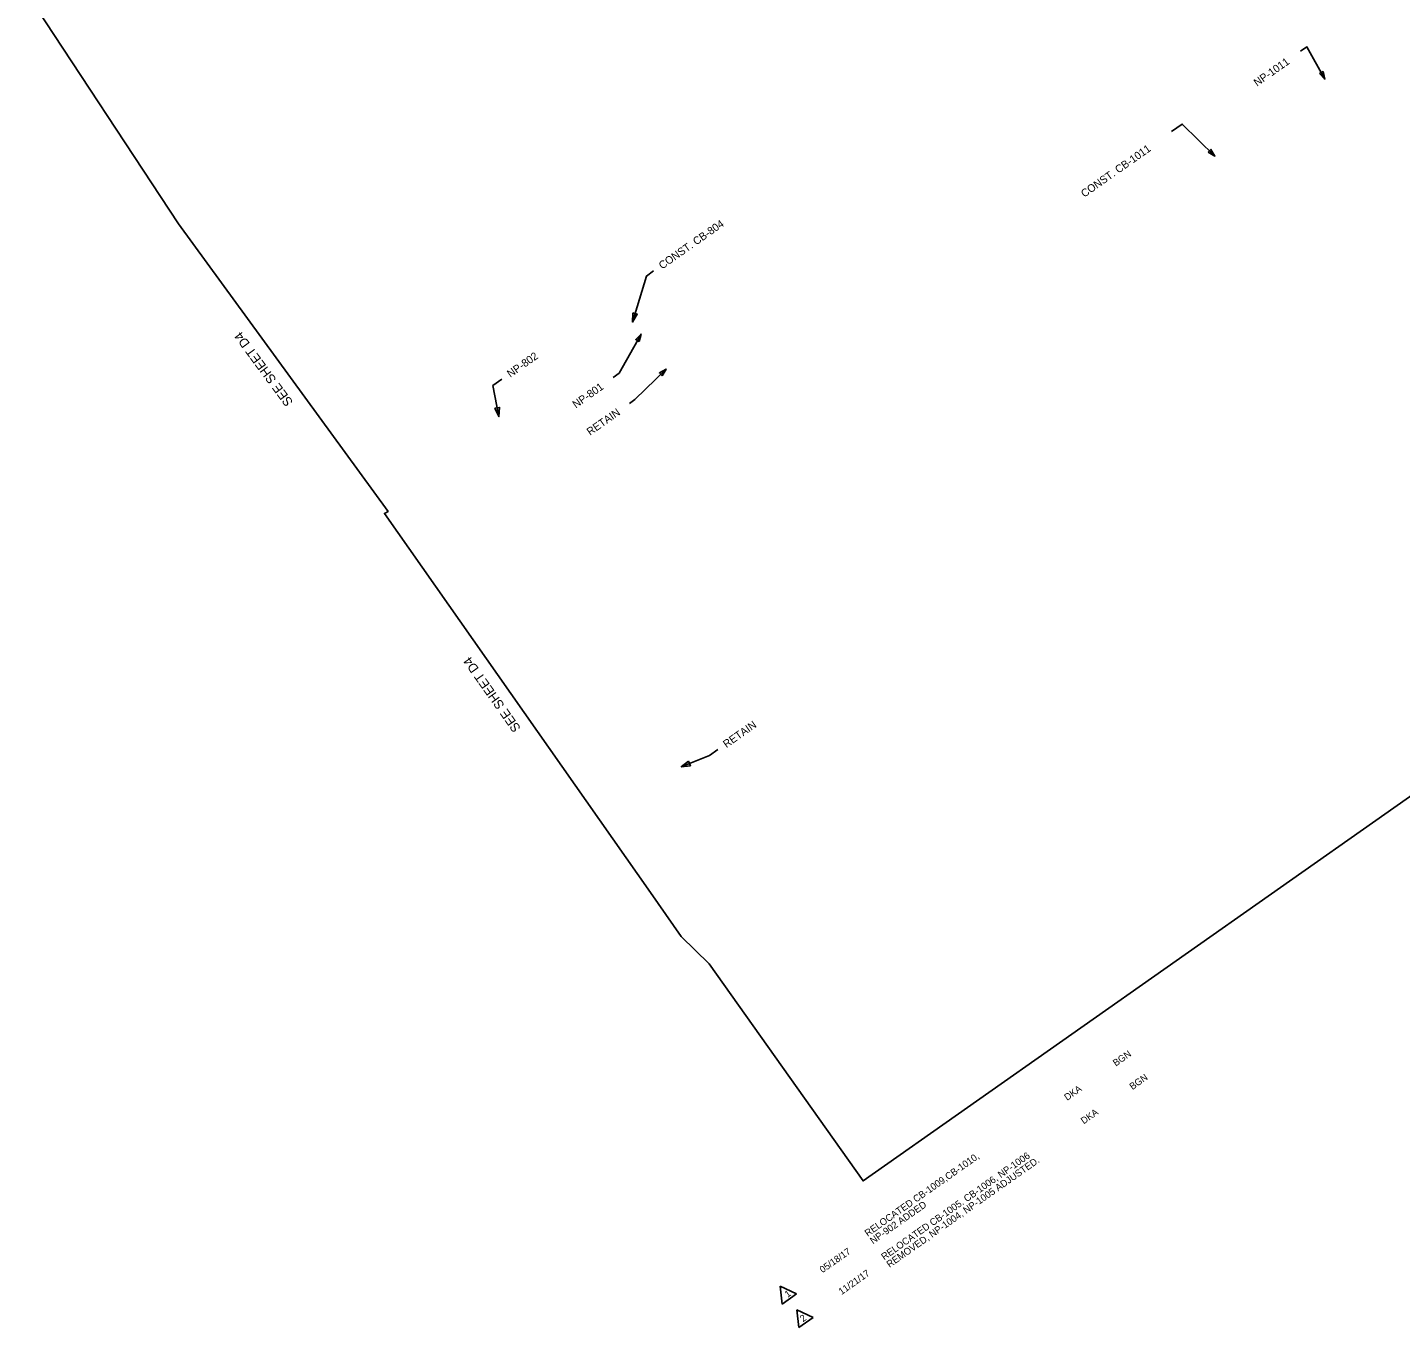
# Model space of a CAD drawing. Extents: x 1607509 to 1609318, y 1091210 to 1092975.
# Drawn here: x 1607509 to 1608401, y 1091231 to 1092076 of the extents above; entities that cross this region are included whole.
import ezdxf

# ---------------------------------------------------------------- set-up
doc = ezdxf.new("R2010")
doc.units = 0
for name, color, linetype in [('Plan_Clip', 7, 'Continuous'), ('RD_SHT_MatchLine', 7, 'Continuous'), ('RD_SHT_TX', 7, 'Continuous'), ('RD_TX_Drainage', 7, 'Continuous')]:
    doc.layers.add(name, color=color, linetype=linetype)

msp = doc.modelspace()

# ---------------------------------------------------------------- linework, layer by layer
at = {"layer": 'Plan_Clip'}
msp.add_lwpolyline([(1607607.31, 1091948.47), (1607743.52, 1091761.59), (1607741.15, 1091760.3), (1607913.93, 1091513.97), (1607933.88, 1091485.53), (1607952.11, 1091467.7), (1608052.12, 1091326.68), (1609136.73, 1092088.95), (1609201.03, 1092156.99), (1609296.24, 1092280.07), (1609089.98, 1092453.43), (1608942.19, 1092657.38), (1608947.36, 1092661.14), (1608865.54, 1092773.4), (1608741.72, 1092932.33), (1608620.57, 1092846.38), (1608601.84, 1092872.78), (1607509.19, 1092097.55)], close=True, dxfattribs=at)
msp.add_lwpolyline([(1607607.31, 1091948.47), (1607743.52, 1091761.59), (1607741.15, 1091760.3), (1607913.93, 1091513.97), (1607933.88, 1091485.53), (1607952.11, 1091467.7), (1608052.12, 1091326.68), (1609136.73, 1092088.95), (1609201.03, 1092156.99), (1609296.24, 1092280.07), (1609089.98, 1092453.43), (1608942.19, 1092657.38), (1608947.36, 1092661.14), (1608865.54, 1092773.4), (1608741.72, 1092932.33), (1608620.57, 1092846.38), (1608601.84, 1092872.78), (1607509.19, 1092097.55)], close=True, dxfattribs=at)
msp.add_lwpolyline([(1607607.31, 1091948.47), (1607743.52, 1091761.59), (1607741.15, 1091760.3), (1607913.93, 1091513.97), (1607933.88, 1091485.53), (1607952.11, 1091467.7), (1608052.12, 1091326.68), (1609136.73, 1092088.95), (1609201.03, 1092156.99), (1609296.24, 1092280.07), (1609089.98, 1092453.43), (1608942.19, 1092657.38), (1608947.36, 1092661.14), (1608865.54, 1092773.4), (1608741.72, 1092932.33), (1608620.57, 1092846.38), (1608601.84, 1092872.78), (1607509.19, 1092097.55)], close=True, dxfattribs=at)
msp.add_lwpolyline([(1607607.31, 1091948.47), (1607743.52, 1091761.59), (1607741.15, 1091760.3), (1607913.93, 1091513.97), (1607933.88, 1091485.53), (1607952.11, 1091467.7), (1608052.12, 1091326.68), (1609136.73, 1092088.95), (1609201.03, 1092156.99), (1609296.24, 1092280.07), (1609089.98, 1092453.43), (1608942.19, 1092657.38), (1608947.36, 1092661.14), (1608865.54, 1092773.4), (1608741.72, 1092932.33), (1608620.57, 1092846.38), (1608601.84, 1092872.78), (1607509.19, 1092097.55)], close=True, dxfattribs=at)
msp.add_lwpolyline([(1607607.31, 1091948.47), (1607743.52, 1091761.59), (1607741.15, 1091760.3), (1607913.93, 1091513.97), (1607933.88, 1091485.53), (1607952.11, 1091467.7), (1608052.12, 1091326.68), (1609136.73, 1092088.95), (1609201.03, 1092156.99), (1609296.24, 1092280.07), (1609089.98, 1092453.43), (1608942.19, 1092657.38), (1608947.36, 1092661.14), (1608865.54, 1092773.4), (1608741.72, 1092932.33), (1608620.57, 1092846.38), (1608601.84, 1092872.78), (1607509.19, 1092097.55)], close=True, dxfattribs=at)
at = {"layer": 'RD_SHT_TX'}
for p, q in [((1608008.81, 1091253.29), (1607998.31, 1091258.3)), ((1607998.31, 1091258.3), (1607999.5, 1091246.73)), ((1607999.5, 1091246.73), (1608008.81, 1091253.29)), ((1608019.58, 1091238), (1608009.08, 1091243.02)), ((1608009.08, 1091243.02), (1608010.27, 1091231.44)), ((1608010.27, 1091231.44), (1608019.58, 1091238))]:
    msp.add_line(p, q, dxfattribs=at)
at = {"layer": 'RD_TX_Drainage'}
for points in [[(1608336.38, 1092060.53), (1608340.45, 1092063.4), (1608352.12, 1092042.5)], [(1608252.54, 1092008.41), (1608259.46, 1092013.28), (1608280.64, 1091992.47)], [(1607916.01, 1091917.88), (1607911.3, 1091914.56), (1607902.25, 1091884.64)], [(1607889.74, 1091848.62), (1607893.61, 1091851.35), (1607907.83, 1091876.85)], [(1607900.23, 1091831.76), (1607903.88, 1091834.32), (1607924.07, 1091854.1)], [(1607817.41, 1091847.56), (1607811.54, 1091843.42), (1607815.51, 1091823.23)], [(1607957.77, 1091606.94), (1607952.2, 1091603.02), (1607933.94, 1091595.73)]]:
    msp.add_lwpolyline(points, dxfattribs=at)
for points in [[(1608348.64, 1092046.09), (1608352.12, 1092042.5), (1608350.9, 1092047.35)], [(1608276.29, 1091994.93), (1608280.64, 1091992.47), (1608278.1, 1091996.78)], [(1607902.44, 1091890.64), (1607902.25, 1091884.64), (1607905.41, 1091889.74)], [(1607906.61, 1091872), (1607907.83, 1091876.85), (1607904.35, 1091873.26)], [(1607921.53, 1091849.8), (1607924.07, 1091854.1), (1607919.72, 1091851.65)], [(1607812.87, 1091828.61), (1607815.51, 1091823.23), (1607815.92, 1091829.21)], [(1607938.75, 1091599.32), (1607933.94, 1091595.73), (1607939.9, 1091596.44)]]:
    msp.add_lwpolyline(points, close=True, dxfattribs=at)

# ---------------------------------------------------------------- texts
at = {"layer": 'RD_SHT_MatchLine'}
for rotation, p in [(126.38123, (1607682.04, 1091832.65)), (125.21745, (1607829.96, 1091620.81))]:
    msp.add_text('SEE SHEET D4', height=6, rotation=rotation, dxfattribs=at).set_placement(p)
at = {"layer": 'RD_SHT_TX'}
for s, height, p in [('BGN', 4.4, (1608216.31, 1091400.93)), ('BGN', 4.4, (1608227.08, 1091385.65)), ('DKA', 4.4, (1608184.68, 1091378.65)), ('DKA', 4.4, (1608195.45, 1091363.37)), ('RELOCATED CB-1009,CB-1010,', 4.5, (1608055.08, 1091290.32)), ('RELOCATED CB-1005. CB-1006, NP-1006', 4.5, (1608065.85, 1091275.03)), ('REMOVED, NP-1004, NP-1005 ADJUSTED.', 4.5, (1608069.3, 1091270.14)), ('NP-902 ADDED ', 4.5, (1608058.53, 1091285.43)), ('05/18/17', 4.4, (1608025.77, 1091266.69)), ('11/21/17', 4.4, (1608038.11, 1091252.5)), ('1', 4.4, (1608003.04, 1091250.67)), ('2', 4.4, (1608013.01, 1091234.82))]:
    msp.add_text(s, height=height, rotation=35.16781, dxfattribs=at).set_placement(p)
at = {"layer": 'RD_TX_Drainage'}
for s, p in [('NP-1011', (1608308.05, 1092037.51)), ('CONST. CB-1011', (1608195.82, 1091965.39)), ('CONST. CB-804', (1607921.53, 1091918.71)), ('NP-802', (1607822.94, 1091848.39)), ('NP-801', (1607865.46, 1091828.46)), ('RETAIN', (1607874.73, 1091810.73)), ('RETAIN', (1607963.3, 1091607.78))]:
    msp.add_text(s, height=5, rotation=35.16619, dxfattribs=at).set_placement(p)

doc.saveas('drawing.dxf')
